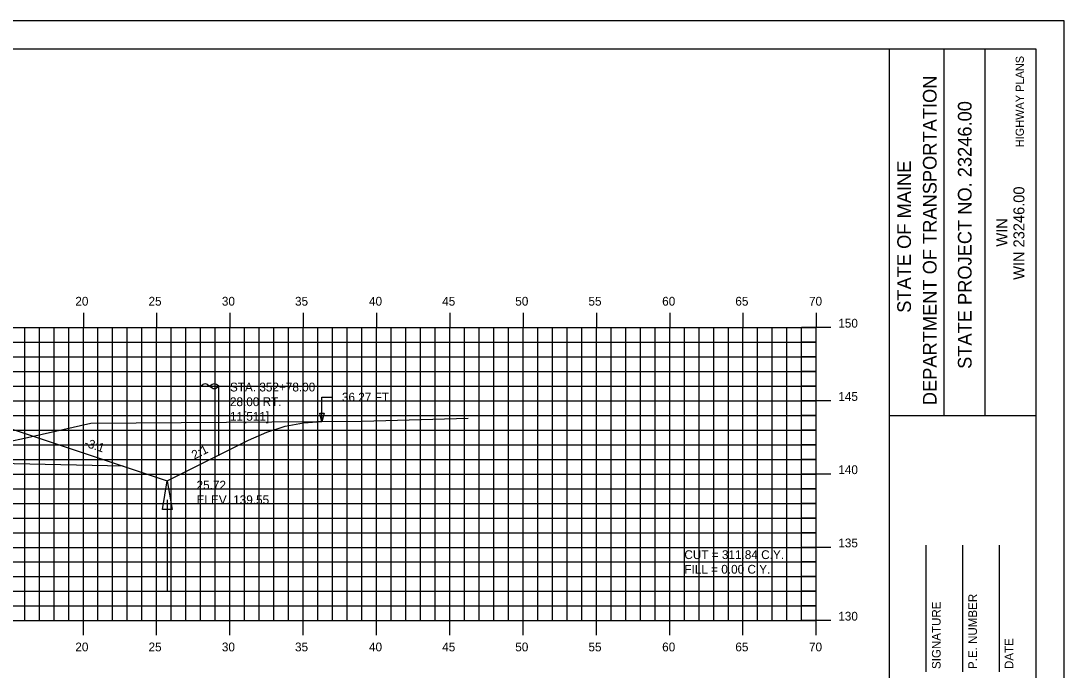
# Model space of a CAD drawing. Extents: x 1144972 to 1145142, y 608981 to 609091.
# Drawn here: x 1145071.1 to 1145142.3, y 609047 to 609091.3 of the extents above; entities that cross this region are included whole.
import ezdxf

# ---------------------------------------------------------------- set-up
doc = ezdxf.new("R2010")
doc.units = 0
for name, color, linetype in [('ANNOTATION', 7, 'Continuous'), ('BORDER', 7, 'Continuous'), ('D_Drainage_Ditch_Line', 7, 'Continuous'), ('D_Roadway_SlopeLines', 7, 'Continuous'), ('D_Roadway_SubGrade', 7, 'Continuous'), ('D_Text_Standard', 7, 'Continuous'), ('D_Utilities_Pole_Joint_Rt', 7, 'Continuous'), ('H_V ANNOTATION', 7, 'Continuous'), ('HIGHWAY_TITLE', 7, 'Continuous'), ('MAJOR', 7, 'Continuous'), ('MINOR', 7, 'Continuous'), ('PLOT BOUNDARY', 7, 'Continuous'), ('S_Roadway_Centerline', 7, 'Continuous')]:
    doc.layers.add(name, color=color, linetype=linetype)

msp = doc.modelspace()

# ---------------------------------------------------------------- linework, layer by layer
msp.add_lwpolyline([(1145017.869, 609064.526), (1145019.119, 609064.447), (1145020.369, 609064.213), (1145021.619, 609063.822), (1145022.869, 609063.275), (1145029.651, 609059.884), (1145032.651, 609060.884), (1145040.374, 609063.458), (1145040.375, 609063.458), (1145044.375, 609063.618), (1145055.375, 609063.838), (1145066.375, 609063.618), (1145070.375, 609063.458), (1145078.099, 609060.884), (1145081.099, 609059.884), (1145086.647, 609062.658), (1145087.897, 609063.206), (1145089.147, 609063.599), (1145090.397, 609063.839), (1145091.647, 609063.924)])
at = {"layer": 'BORDER'}
for p, q in [((1145130.376, 608984.335), (1145130.376, 609089.335)), ((1145134.104, 609064.332), (1145134.104, 609089.332)), ((1145136.899, 609064.332), (1145136.899, 609089.332)), ((1145130.377, 609064.329), (1145140.376, 609064.329)), ((1145132.876, 609046.838), (1145132.876, 609055.485)), ((1145135.376, 609046.838), (1145135.376, 609055.485)), ((1145137.876, 609046.838), (1145137.876, 609055.485))]:
    msp.add_line(p, q, dxfattribs=at)
msp.add_lwpolyline([(1144980.376, 608984.335), (1145140.376, 608984.335), (1145140.376, 609089.335), (1144980.376, 609089.335)], close=True, dxfattribs=at)
at = {"layer": 'D_Drainage_Ditch_Line'}
msp.add_line((1145081.099, 609058.572), (1145081.099, 609052.328), dxfattribs=at)
msp.add_lwpolyline([(1145081.427, 609057.915), (1145080.771, 609057.915), (1145081.099, 609059.884)], close=True, dxfattribs=at)
at = {"layer": 'D_Roadway_SlopeLines'}
for points in [[(1145081.099, 609059.884), (1145086.647, 609062.658), (1145087.897, 609063.206), (1145089.147, 609063.599), (1145090.397, 609063.839), (1145091.647, 609063.924)], [(1145078.099, 609060.884), (1145081.099, 609059.884)]]:
    msp.add_lwpolyline(points, dxfattribs=at)
at = {"layer": 'D_Roadway_SubGrade'}
msp.add_lwpolyline([(1145066.375, 609063.202), (1145066.375, 609063.368), (1145070.375, 609063.208), (1145070.375, 609063.458), (1145070.376, 609063.458), (1145078.099, 609060.884), (1145066.375, 609061.118)], close=True, dxfattribs=at)
at = {"layer": 'D_Text_Standard'}
msp.add_lwpolyline([(1145091.647, 609063.908), (1145091.655, 609065.587), (1145092.335, 609065.587)], dxfattribs=at)
msp.add_lwpolyline([(1145091.647, 609063.908), (1145091.504, 609064.491), (1145091.795, 609064.489)], close=True, dxfattribs=at)
at = {"layer": 'D_Utilities_Pole_Joint_Rt'}
for p, q in [((1145083.375, 609066.337), (1145083.532, 609066.447)), ((1145083.375, 609061.579), (1145083.375, 609066.337)), ((1145083.844, 609066.447), (1145084, 609066.337)), ((1145084.156, 609066.447), (1145084, 609066.337)), ((1145084, 609066.337), (1145084.156, 609066.226)), ((1145084.625, 609066.337), (1145084.469, 609066.447)), ((1145084.469, 609066.226), (1145084.625, 609066.337)), ((1145084.625, 609061.579), (1145084.625, 609066.337))]:
    msp.add_line(p, q, dxfattribs=at)
for centre, start, end in [((1145083.688, 609066.226), 90, 125.26439), ((1145083.688, 609066.226), 54.73561, 90), ((1145084.313, 609066.226), 90, 125.26439), ((1145084.313, 609066.447), 234.73561, 270), ((1145084.313, 609066.226), 54.73561, 90), ((1145084.313, 609066.447), 270, 305.26439)]:
    msp.add_arc(centre, 0.271, start, end, dxfattribs=at)
at = {"layer": 'MAJOR'}
for p, q in [((1145075.375, 609071.337), (1145075.375, 609070.335)), ((1145080.375, 609071.337), (1145080.375, 609070.335)), ((1145085.375, 609071.337), (1145085.375, 609070.335)), ((1145090.375, 609071.337), (1145090.375, 609070.335)), ((1145095.375, 609071.337), (1145095.375, 609070.335)), ((1145100.375, 609071.337), (1145100.375, 609070.335)), ((1145105.375, 609071.337), (1145105.375, 609070.335)), ((1145110.375, 609071.337), (1145110.375, 609070.335)), ((1145115.375, 609071.337), (1145115.375, 609070.335)), ((1145120.375, 609071.337), (1145120.375, 609070.335)), ((1145125.375, 609071.337), (1145125.375, 609070.335)), ((1144985.375, 609070.335), (1145125.375, 609070.335)), ((1144985.375, 609070.335), (1145125.375, 609070.335)), ((1145075.375, 609050.335), (1145075.375, 609070.335)), ((1145080.375, 609050.335), (1145080.375, 609070.335)), ((1145085.375, 609050.335), (1145085.375, 609070.335)), ((1145090.375, 609050.335), (1145090.375, 609070.335)), ((1145095.375, 609050.335), (1145095.375, 609070.335)), ((1145100.375, 609050.335), (1145100.375, 609070.335)), ((1145105.375, 609050.335), (1145105.375, 609070.335)), ((1145110.375, 609050.335), (1145110.375, 609070.335)), ((1145115.375, 609050.335), (1145115.375, 609070.335)), ((1145120.375, 609050.335), (1145120.375, 609070.335)), ((1145126.377, 609070.335), (1145124.373, 609070.335)), ((1145125.375, 609050.335), (1145125.375, 609070.335)), ((1145125.375, 609050.335), (1145125.375, 609070.335)), ((1144985.375, 609065.335), (1145125.375, 609065.335)), ((1145126.377, 609065.335), (1145124.373, 609065.335)), ((1144985.375, 609060.335), (1145125.375, 609060.335)), ((1145126.377, 609060.335), (1145124.373, 609060.335)), ((1144985.375, 609055.335), (1145125.375, 609055.335)), ((1145126.377, 609055.335), (1145124.373, 609055.335)), ((1144985.375, 609050.335), (1145125.375, 609050.335)), ((1144985.375, 609050.335), (1145125.375, 609050.335)), ((1145075.375, 609049.333), (1145075.375, 609050.335)), ((1145080.375, 609049.333), (1145080.375, 609050.335)), ((1145085.375, 609049.333), (1145085.375, 609050.335)), ((1145090.375, 609049.333), (1145090.375, 609050.335)), ((1145095.375, 609049.333), (1145095.375, 609050.335)), ((1145100.375, 609049.333), (1145100.375, 609050.335)), ((1145105.375, 609049.333), (1145105.375, 609050.335)), ((1145110.375, 609049.333), (1145110.375, 609050.335)), ((1145115.375, 609049.333), (1145115.375, 609050.335)), ((1145120.375, 609049.333), (1145120.375, 609050.335)), ((1145126.377, 609050.335), (1145124.373, 609050.335)), ((1145125.375, 609049.333), (1145125.375, 609050.335))]:
    msp.add_line(p, q, dxfattribs=at)
at = {"layer": 'MINOR'}
for p, q in [((1145071.375, 609050.335), (1145071.375, 609070.335)), ((1145072.375, 609050.335), (1145072.375, 609070.335)), ((1145073.375, 609050.335), (1145073.375, 609070.335)), ((1145074.375, 609050.335), (1145074.375, 609070.335)), ((1145076.375, 609050.335), (1145076.375, 609070.335)), ((1145077.375, 609050.335), (1145077.375, 609070.335)), ((1145078.375, 609050.335), (1145078.375, 609070.335)), ((1145079.375, 609050.335), (1145079.375, 609070.335)), ((1145081.375, 609050.335), (1145081.375, 609070.335)), ((1145082.375, 609050.335), (1145082.375, 609070.335)), ((1145083.375, 609050.335), (1145083.375, 609070.335)), ((1145084.375, 609050.335), (1145084.375, 609070.335)), ((1145086.375, 609050.335), (1145086.375, 609070.335)), ((1145087.375, 609050.335), (1145087.375, 609070.335)), ((1145088.375, 609050.335), (1145088.375, 609070.335)), ((1145089.375, 609050.335), (1145089.375, 609070.335)), ((1145091.375, 609050.335), (1145091.375, 609070.335)), ((1145092.375, 609050.335), (1145092.375, 609070.335)), ((1145093.375, 609050.335), (1145093.375, 609070.335)), ((1145094.375, 609050.335), (1145094.375, 609070.335)), ((1145096.375, 609050.335), (1145096.375, 609070.335)), ((1145097.375, 609050.335), (1145097.375, 609070.335)), ((1145098.375, 609050.335), (1145098.375, 609070.335)), ((1145099.375, 609050.335), (1145099.375, 609070.335)), ((1145101.375, 609050.335), (1145101.375, 609070.335)), ((1145102.375, 609050.335), (1145102.375, 609070.335)), ((1145103.375, 609050.335), (1145103.375, 609070.335)), ((1145104.375, 609050.335), (1145104.375, 609070.335)), ((1145106.375, 609050.335), (1145106.375, 609070.335)), ((1145107.375, 609050.335), (1145107.375, 609070.335)), ((1145108.375, 609050.335), (1145108.375, 609070.335)), ((1145109.375, 609050.335), (1145109.375, 609070.335)), ((1145111.375, 609050.335), (1145111.375, 609070.335)), ((1145112.375, 609050.335), (1145112.375, 609070.335)), ((1145113.375, 609050.335), (1145113.375, 609070.335)), ((1145114.375, 609050.335), (1145114.375, 609070.335)), ((1145116.375, 609050.335), (1145116.375, 609070.335)), ((1145117.375, 609050.335), (1145117.375, 609070.335)), ((1145118.375, 609050.335), (1145118.375, 609070.335)), ((1145119.375, 609050.335), (1145119.375, 609070.335)), ((1145121.375, 609050.335), (1145121.375, 609070.335)), ((1145122.375, 609050.335), (1145122.375, 609070.335)), ((1145123.375, 609050.335), (1145123.375, 609070.335)), ((1145124.375, 609050.335), (1145124.375, 609070.335)), ((1144985.375, 609069.335), (1145125.375, 609069.335)), ((1145125.375, 609069.335), (1145124.373, 609069.335)), ((1144985.375, 609068.335), (1145125.375, 609068.335)), ((1145125.375, 609068.335), (1145124.373, 609068.335)), ((1144985.375, 609067.335), (1145125.375, 609067.335)), ((1145125.375, 609067.335), (1145124.373, 609067.335)), ((1144985.375, 609066.335), (1145125.375, 609066.335)), ((1145125.375, 609066.335), (1145124.373, 609066.335)), ((1144985.375, 609064.335), (1145125.375, 609064.335)), ((1145125.375, 609064.335), (1145124.373, 609064.335)), ((1144985.375, 609063.335), (1145125.375, 609063.335)), ((1145125.375, 609063.335), (1145124.373, 609063.335)), ((1144985.375, 609062.335), (1145125.375, 609062.335)), ((1145125.375, 609062.335), (1145124.373, 609062.335)), ((1144985.375, 609061.335), (1145125.375, 609061.335)), ((1145125.375, 609061.335), (1145124.373, 609061.335)), ((1144985.375, 609059.335), (1145125.375, 609059.335)), ((1145125.375, 609059.335), (1145124.373, 609059.335)), ((1144985.375, 609058.335), (1145125.375, 609058.335)), ((1145125.375, 609058.335), (1145124.373, 609058.335)), ((1144985.375, 609057.335), (1145125.375, 609057.335)), ((1145125.375, 609057.335), (1145124.373, 609057.335)), ((1144985.375, 609056.335), (1145125.375, 609056.335)), ((1145125.375, 609056.335), (1145124.373, 609056.335)), ((1144985.375, 609054.335), (1145125.375, 609054.335)), ((1145125.375, 609054.335), (1145124.373, 609054.335)), ((1144985.375, 609053.335), (1145125.375, 609053.335)), ((1145125.375, 609053.335), (1145124.373, 609053.335)), ((1144985.375, 609052.335), (1145125.375, 609052.335)), ((1145125.375, 609052.335), (1145124.373, 609052.335)), ((1144985.375, 609051.335), (1145125.375, 609051.335)), ((1145125.375, 609051.335), (1145124.373, 609051.335))]:
    msp.add_line(p, q, dxfattribs=at)
at = {"layer": 'PLOT BOUNDARY'}
msp.add_lwpolyline([(1144972.282, 608981.276), (1145142.282, 608981.276), (1145142.282, 609091.276), (1144972.282, 609091.276)], close=True, dxfattribs=at)
at = {"layer": 'S_Roadway_Centerline'}
msp.add_lwpolyline([(1145001.997, 609064.533), (1145021.959, 609064.524), (1145026.689, 609064.539), (1145033.328, 609063.015), (1145034.845, 609062.632), (1145035.408, 609062.786), (1145038.043, 609063.382), (1145039.736, 609063.551), (1145040.242, 609063.584), (1145049.415, 609063.888), (1145051.636, 609063.943), (1145061.011, 609063.662), (1145062.985, 609063.582), (1145063.485, 609063.534), (1145067.713, 609063.215), (1145069.391, 609062.729), (1145070.304, 609062.563), (1145071.368, 609062.797), (1145075.896, 609063.823), (1145094.4, 609063.941), (1145101.628, 609064.155)], dxfattribs=at)

# ---------------------------------------------------------------- texts
at = {"layer": 'ANNOTATION'}
for s, rotation, p in [('-3:1', 341.56521, (1145075.387, 609062.242)), ('2:1', 26.56505, (1145082.946, 609061.325))]:
    msp.add_text(s, height=0.6, rotation=rotation, dxfattribs=at).set_placement(p)
at = {"layer": 'BORDER'}
for s, height, p in [('DEPARTMENT OF TRANSPORTATION', 0.93176, (1145133.582, 609065.041)), ('STATE PROJECT NO. 23246.00', 0.93176, (1145135.968, 609067.517)), ('STATE OF MAINE', 0.93176, (1145131.831, 609071.347)), ('WIN 23246.00', 0.74527, (1145139.571, 609073.596)), ('WIN', 0.7453, (1145138.412, 609075.865)), ('P.E. NUMBER', 0.59055, (1145136.336, 609047.03)), ('SIGNATURE', 0.5906, (1145133.856, 609047.03)), ('DATE', 0.5906, (1145138.817, 609047.03))]:
    msp.add_text(s, height=height, rotation=90, dxfattribs=at).set_placement(p)
at = {"layer": 'D_Text_Standard'}
for s, p in [('STA. 352+78.00', (1145085.375, 609065.977)), ('28.00 RT.', (1145085.375, 609064.975)), ('36.27 FT', (1145093.015, 609065.287)), ('11[511] ', (1145085.375, 609063.979)), ('25.72', (1145083.099, 609059.284)), ('ELEV. 139.55', (1145083.099, 609058.282)), ('CUT = 311.84 C.Y.', (1145116.375, 609054.535)), ('FILL = 0.00 C.Y.', (1145116.375, 609053.539))]:
    msp.add_text(s, height=0.6, dxfattribs=at).set_placement(p)
at = {"layer": 'H_V ANNOTATION'}
for s, p in [('20', (1145074.829, 609071.835)), ('25', (1145079.821, 609071.835)), ('30', (1145084.824, 609071.835)), ('35', (1145089.816, 609071.835)), ('40', (1145094.862, 609071.835)), ('45', (1145099.854, 609071.835)), ('50', (1145104.84, 609071.835)), ('55', (1145109.832, 609071.835)), ('60', (1145114.862, 609071.835)), ('65', (1145119.854, 609071.835)), ('70', (1145124.878, 609071.835)), ('150', (1145126.875, 609070.335)), ('145', (1145126.875, 609065.335)), ('140', (1145126.875, 609060.335)), ('135', (1145126.875, 609055.335)), ('130', (1145126.875, 609050.335)), ('20', (1145074.829, 609048.235)), ('25', (1145079.821, 609048.235)), ('30', (1145084.824, 609048.235)), ('35', (1145089.816, 609048.235)), ('40', (1145094.862, 609048.235)), ('45', (1145099.854, 609048.235)), ('50', (1145104.84, 609048.235)), ('55', (1145109.832, 609048.235)), ('60', (1145114.862, 609048.235)), ('65', (1145119.854, 609048.235)), ('70', (1145124.878, 609048.235))]:
    msp.add_text(s, height=0.6, dxfattribs=at).set_placement(p)
at = {"layer": 'HIGHWAY_TITLE'}
msp.add_text('HIGHWAY PLANS', height=0.55901, rotation=90, dxfattribs=at).set_placement((1145139.534, 609082.65))

doc.saveas('drawing.dxf')
